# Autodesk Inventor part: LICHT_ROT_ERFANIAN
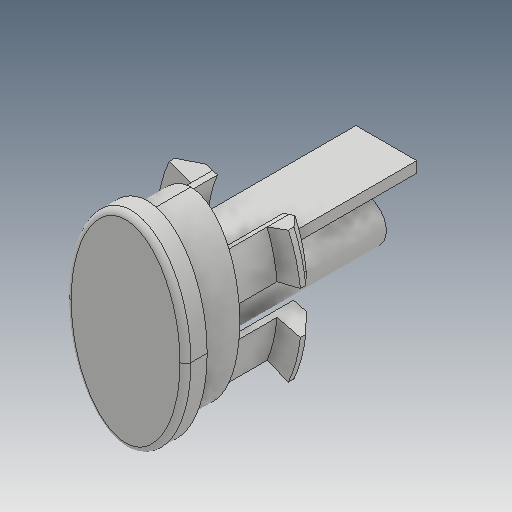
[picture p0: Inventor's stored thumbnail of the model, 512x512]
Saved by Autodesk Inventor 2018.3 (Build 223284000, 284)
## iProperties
Created: 2019-01
Part Number: LICHT_ROT_ERFANIAN
Material: Generisch
Document SubType Name: Modeling
Designer: zand
Density: 1 g/cm^3
Appearance: Vorgabe
Mass: 0.773677 g
Surface Area: 18.322 cm^2
Volume: 0.773677 cm^3
Author: zand
Revision Number: 14LAST_VERSION
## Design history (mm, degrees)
feature "Basis1"
node "Volumenkörper1"
